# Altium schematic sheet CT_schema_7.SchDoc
size 411 x 382 mm
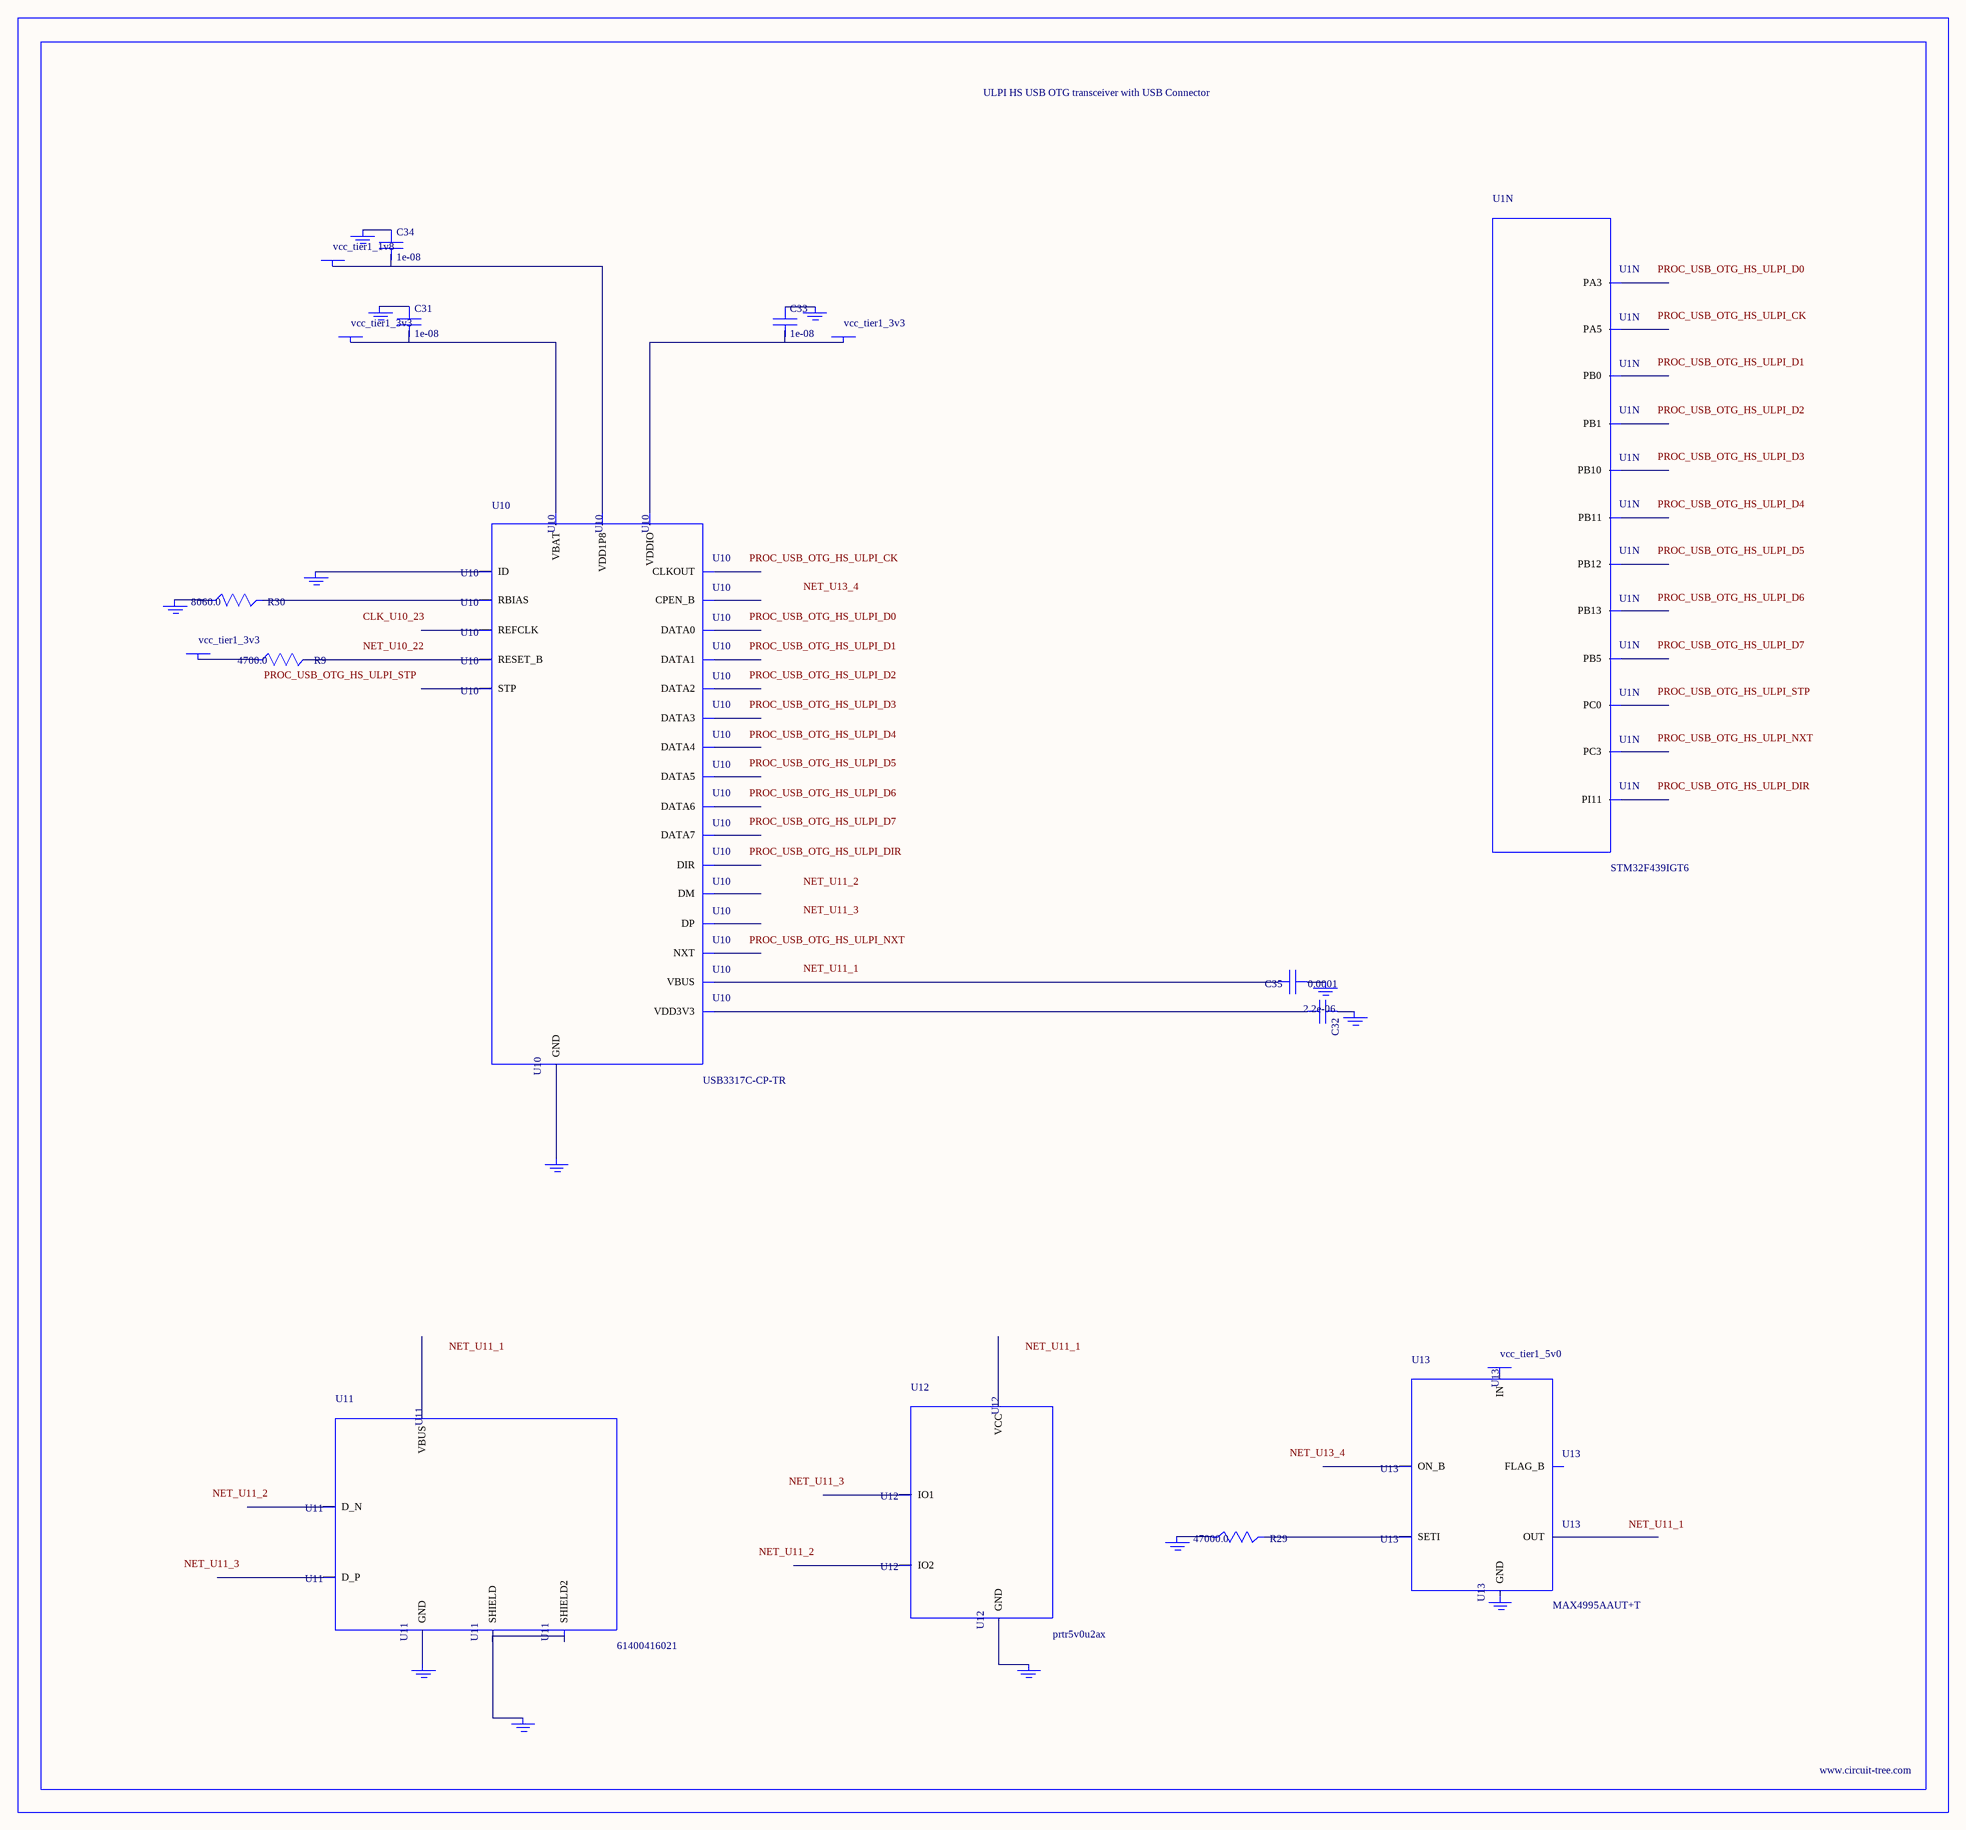
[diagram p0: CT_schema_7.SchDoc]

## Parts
BORDER6  (no value)
C31  1e-08  [C0402]
C32  2.2e-06  [C0603]
C33  1e-08  [C0402]
C34  1e-08  [C0402]
C35  0.0001  [R0603]
GND_INSTANCE_6_0  (no value)
GND_INSTANCE_6_1  (no value)
GND_INSTANCE_6_2  (no value)
GND_INSTANCE_6_3  (no value)
GND_INSTANCE_6_4  (no value)
GND_INSTANCE_6_5  (no value)
GND_INSTANCE_6_6  (no value)
GND_INSTANCE_6_7  (no value)
GND_INSTANCE_6_8  (no value)
GND_INSTANCE_6_9  (no value)
GND_INSTANCE_6_10  (no value)
GND_INSTANCE_6_11  (no value)
GND_INSTANCE_6_12  (no value)
POWER_INSTANCE_6_0  vcc_tier1_3v3
POWER_INSTANCE_6_1  vcc_tier1_3v3
POWER_INSTANCE_6_2  vcc_tier1_1v8
POWER_INSTANCE_6_3  vcc_tier1_3v3
POWER_INSTANCE_6_4  vcc_tier1_5v0
R9  4700.0  [R0603]
R29  47000.0  [R0603]
R30  8060.0  [R0603]
U1  STM32F439IGT6  [LQFP176]  (part N of 14)
U10  USB3317C-CP-TR  [QFN-24]
U11  61400416021  [USB-A-H]
U12  prtr5v0u2ax  [SOT143B]
U13  MAX4995AAUT+T  [SOT-23-6]

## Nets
NetC31_1: C31.1 GND_INSTANCE_6_2.0(GND)
NetC31_2: C31.2 POWER_INSTANCE_6_0.0(PWR) U10.3(VBAT)
NetC32_1: C32.1 GND_INSTANCE_6_3.0(GND)
NetC32_2: C32.2 U10.4(VDD3V3)
NetC33_1: C33.1 GND_INSTANCE_6_4.0(GND)
NetC33_2: C33.2 POWER_INSTANCE_6_1.0(PWR) U10.17(VDDIO)
NetC34_1: C34.1 GND_INSTANCE_6_5.0(GND)
NetC34_2: C34.2 POWER_INSTANCE_6_2.0(PWR) U10.21(VDD1P8)
NetC35_1: C35.1 GND_INSTANCE_6_1.0(GND)
NetC35_2: C35.2 U10.2(VBUS)
NetGND_INSTANCE_6_0_0: GND_INSTANCE_6_0.0(GND) U10.1(ID)
NetGND_INSTANCE_6_6_0: GND_INSTANCE_6_6.0(GND) R30.1
NetGND_INSTANCE_6_7_0: GND_INSTANCE_6_7.0(GND) U10.25(GND)
NetGND_INSTANCE_6_8_0: GND_INSTANCE_6_8.0(GND) U11.5(SHIELD) U11.6(SHIELD2)
NetGND_INSTANCE_6_9_0: GND_INSTANCE_6_9.0(GND) U11.4(GND)
NetGND_INSTANCE_6_10_0: GND_INSTANCE_6_10.0(GND) U12.1(GND)
NetGND_INSTANCE_6_11_0: GND_INSTANCE_6_11.0(GND) R29.1
NetPOWER_INSTANCE_6_3_0: POWER_INSTANCE_6_3.0(PWR) R9.1
NetR9_2: R9.2 U10.22(RESET_B)
NetR29_2: R29.2 U13.3(SETI)
NetR30_2: R30.2 U10.24(RBIAS)

Not connected (* = marked no-connect by the designer): GND_INSTANCE_6_12 0(GND); POWER_INSTANCE_6_4 0(PWR); U1 13(PI11) 32(PC0) 35(PC3) 47(PA3) 51(PA5) 56(PB0) 57(PB1) 79(PB10) 80(PB11) 92(PB12) 93(PB13) 163(PB5); U10 5(DM) 6(DP) 7(CPEN_B) 8(DATA7) 9(DATA6) 10(DATA5) 11(DATA4) 12(CLKOUT) 13(DATA3) 14(DATA2) 15(DATA1) 16(DATA0) 18(NXT) 19(DIR) 20(STP) 23(REFCLK); U11 1(VBUS) 2(D_N) 3(D_P); U12 2(IO1) 3(IO2) 4(VCC); U13 1(OUT) 2(GND) 4(ON_B) 5(IN) 6(FLAG_B)

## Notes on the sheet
- Labels drawn without touching a wire or pin: CLK_U10_23, NET_U10_22, NET_U11_1, NET_U11_2, NET_U11_3, NET_U13_4, PROC_USB_OTG_HS_ULPI_CK, PROC_USB_OTG_HS_ULPI_D0, PROC_USB_OTG_HS_ULPI_D1, PROC_USB_OTG_HS_ULPI_D2, PROC_USB_OTG_HS_ULPI_D3, PROC_USB_OTG_HS_ULPI_D4, PROC_USB_OTG_HS_ULPI_D5, PROC_USB_OTG_HS_ULPI_D6, PROC_USB_OTG_HS_ULPI_D7, PROC_USB_OTG_HS_ULPI_DIR, PROC_USB_OTG_HS_ULPI_NXT, PROC_USB_OTG_HS_ULPI_STP

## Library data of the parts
BORDER6 = BORDER_PAGE6
C31 C33 C34 = C0402C103K3RAC
C32 = C0603C225K8RACTU
C35 = C35
GND_INSTANCE_6_0-GND_INSTANCE_6_12 = GND
POWER_INSTANCE_6_0-POWER_INSTANCE_6_4 = PWR
R9 = RC0603JR-074K7L
R29 = RC0603JR-0747KL
R30 = ERJ-3EKF8061V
